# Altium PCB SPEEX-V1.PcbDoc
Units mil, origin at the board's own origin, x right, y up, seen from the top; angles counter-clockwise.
Board outline 3563 x 2400 mil, 2 copper layers (Top Layer, Bottom Layer); 127 components, 78 nets, 444 pads, 198 vias.
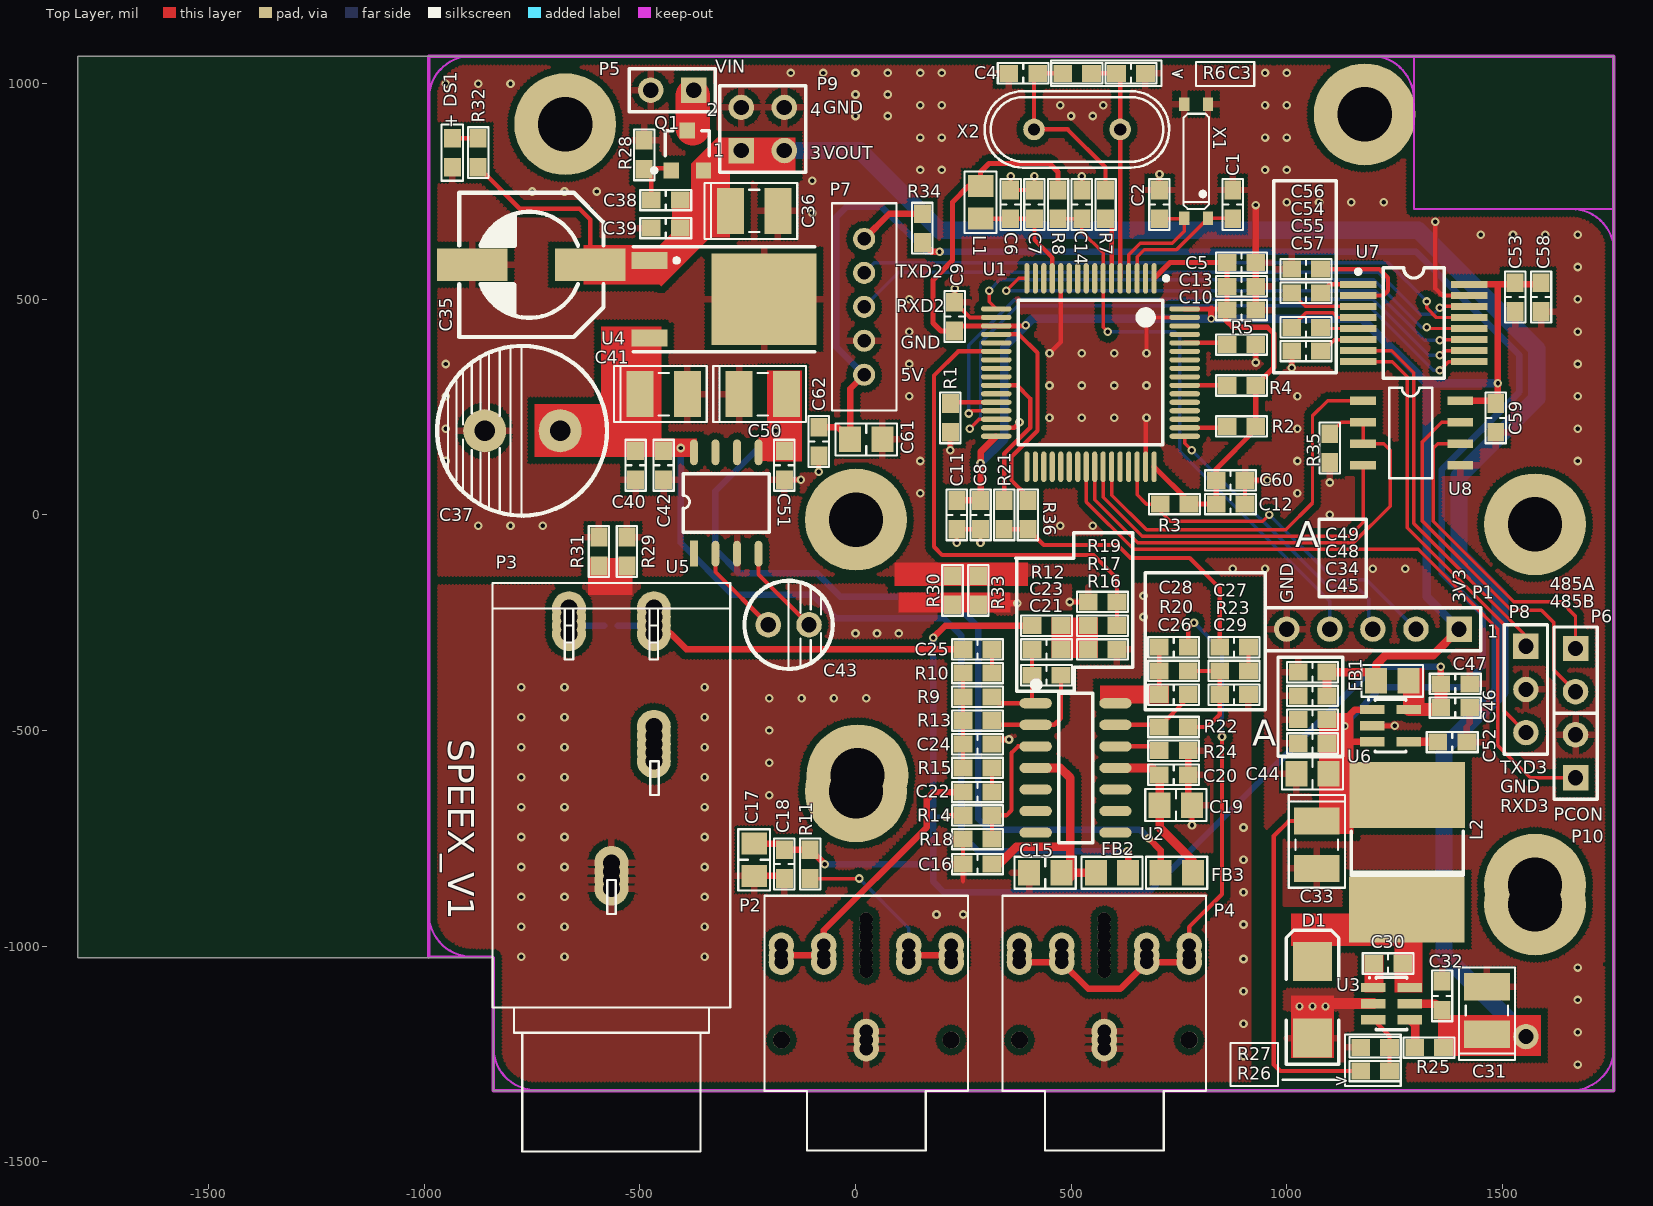
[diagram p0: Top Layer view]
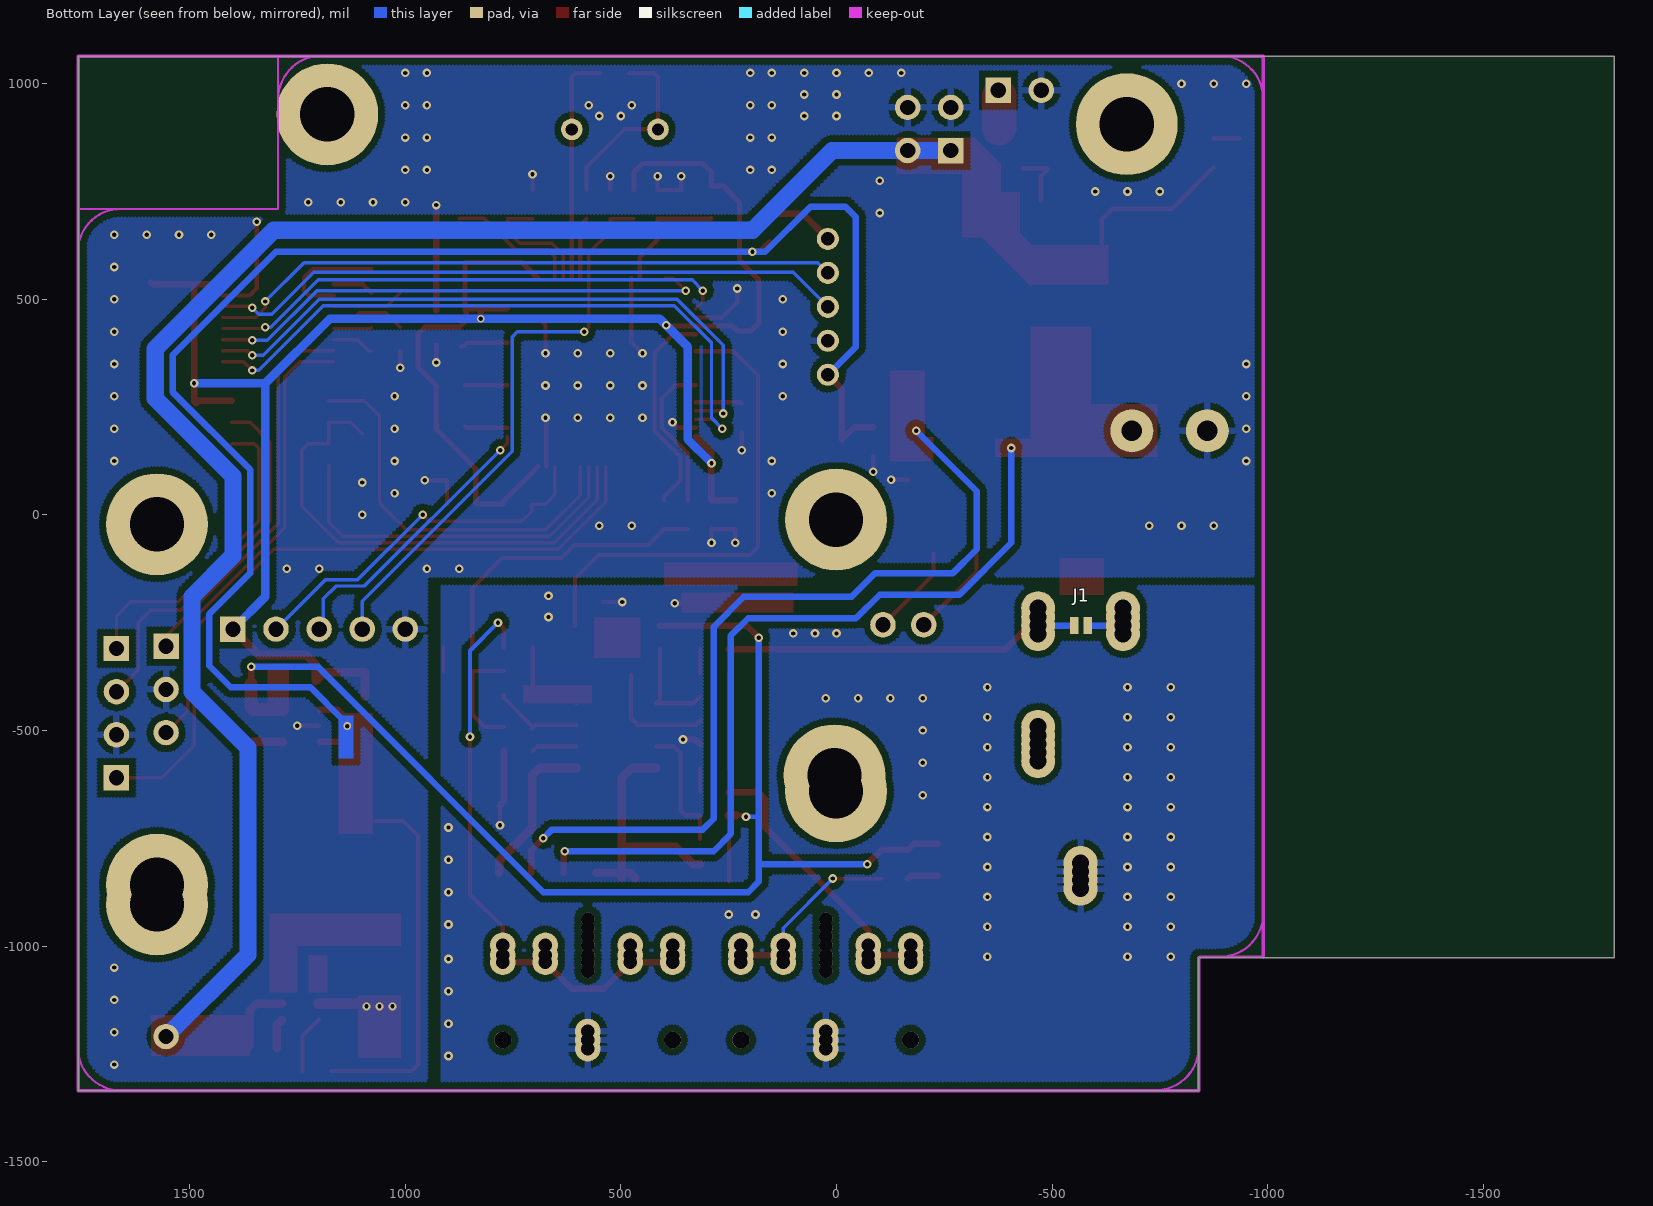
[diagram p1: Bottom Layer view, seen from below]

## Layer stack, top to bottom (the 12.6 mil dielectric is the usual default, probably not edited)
Top Layer: signal copper 1.4
Dielectric: dielectric 12.6, FR-4, Dk 4.8
Bottom Layer: signal copper 1.4

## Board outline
-1804,1064 -1804,-1026 -1803,-1027 -840,-1027 -840,-1336 1759,-1336 1759,1064

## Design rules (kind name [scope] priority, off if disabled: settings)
Clearance Clearance_1 [INPOLYGON] p1: gap=15
Clearance [All] p2: gap=7
ComponentClearance [All] p1: gap=0 collisioncheckmode=3 verticalgap=0 showdistances=FALSE
FabricationTestpoint [(IsPad And (OnTopLayer Or OnBottomLayer))] p1: side=3 testpointundercomponent=TRUE minsize=40 maxsize=100 preferedsize=60 minholesize=0 maxholesize=40 preferedholesize=32 testpointgrid=1 allowsidetop=TRUE allowsidebottom=TRUE usegrid=TRUE gridtolerance=0.01
HoleSize [All] p1: absolutevalues=TRUE maxlimit=200 minlimit=1 maxpercent=80.000 minpercent=20.000
PolygonConnect [IsVia] p1: connectstyle=Direct reliefconductorwidth=10 reliefentries=4 polygonreliefangle="90 Angle"
PolygonConnect PolygonConnect_1 [All] p2: connectstyle=Relief reliefconductorwidth=15 reliefentries=4 polygonreliefangle="90 Angle"
RoomDefinition mcu [InComponentClass('mcu')] p1 off: confinementstyle=ConfineIn formatcopy=TRUE lockcomponents=FALSE outline 4067,1338 4262,1338 4262,1593 4067,1593
RoomDefinition rs232_485 [InComponentClass('rs232_485')] p2 off: confinementstyle=ConfineIn formatcopy=TRUE lockcomponents=FALSE outline 2712,308 5982,308 5982,913 2712,913
RoomDefinition power [InComponentClass('power')] p3 off: confinementstyle=ConfineIn formatcopy=TRUE lockcomponents=FALSE outline 4147,-252 4382,-252 4382,-2 4147,-2
RoomDefinition audio_inout [InComponentClass('audio_inout')] p4 off: confinementstyle=ConfineIn formatcopy=TRUE lockcomponents=FALSE outline 3092,-1387 10067,-1387 10067,-677 3092,-677
RoutingVias [All] p1: holewidth=10 width=20 viastyle="Through Hole" minholewidth=8 minwidth=15 maxholewidth=28 maxwidth=50
SilkscreenOverComponentPads [All] p1: minsilkscreentomaskgap=10
SolderMaskExpansion [All] p1: expansion=4
Width [All] p1: maxlimit=100 minlimit=8 preferedwidth=10
24 further rules are at their usual default settings.

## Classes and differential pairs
component class mcu: C1 C2 C3 C4 C5 C6 C7 C8 C9 C10 C11 C12 C13 C14 C60 C? D? DS? FB? L1 L? P1 P? Q? R1 R2 R3 R4 R5 R6 R7 R8 R? U1 U? X1 X2 X?
component class audio_inout: C15 C16 C17 C18 C19 C20 C21 C22 C23 C24 C25 C26 C27 C28 C29 J1 P2 P3 P4 R9 R10 R11 R12 R13 R14 R15 R16 R17 R18 R19 R20 R21 R22 R23 R24 R36 U2
component class rs232_485: C5 C53 C54 C55 C56 C58 C59 C61 C62 P6 P7 P8 P9 P10 R1 R35 U1 U8
component class power: C6 C7 C31 C33 C34 C35 C36 C37 C38 C39 C40 C41 C42 C43 C44 C45 C46 C47 C48 C49 C50 C51 C52 D1 DS1 FB1 FB2 FB3 L1 P5 Q1 R5 R25 R26 R27 R29 R30 R31 R32 R33 U3 U4 U5 U6

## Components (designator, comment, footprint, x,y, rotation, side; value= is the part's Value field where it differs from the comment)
C1 "6.8pF" C-0603 875,720 r90 top
C2 "6.8pF" C-0603 705,720 r90 top
C3 "20pF" C-0603 639,1024 r0 top
C4 "20pF" C-0603 389,1024 r180 top
C5 "100nF" C-0603 895,585 r180 top
C6 "1uF" C-0603 360,720 r270 top
C7 "100nF" C-0603 415,720 r270 top
C8 "100nF" C-0603 290,0 r90 top
C9 "100nF" C-0603 230,460 r270 top
C10 "100nF" C-0603 895,475 r180 top
C11 "100nF" C-0603 235,0 r90 top
C12 "100nF" C-0603 870,25 r180 top
C13 "10uF" C-0603 895,530 r180 top
C14 "104" C-0603 525,720 r270 top
C15 "10uF" C-0805 440,-830 r180 top
C16 "0.1uF" C-0603 283,-810 r0 top
C17 "10uF" C0805 -235,-800 r90 top
C18 "0.1uF" C-0603 -165,-810 r90 top
C19 "10uF" C-0805 743,-673 r180 top
C20 "0.1uF" C-0603 738,-603 r180 top
C21 "500pF" C-0603 443,-372 r180 top
C22 "10uF" C-0603 283,-643 r0 top
C23 "10uF" C-0603 443,-312 r180 top
C24 "1nF" C-0603 283,-532 r180 top
C25 "10uF" C-0603 283,-312 r0 top
C26 "20pF" C-0603 738,-417 r180 top
C27 "10uF" C-0603 878,-307 r0 top
C28 "10uF" C-0603 738,-307 r0 top
C29 "1nF" C-0603 878,-417 r180 top
C30 "2.2nF" C-0603 1235.46,-1040.54 r0 top
C31 "10uF/25V" C-1210 1464.46,-1149.54 r90 top
C32 "0.01uF" C-0603 1360.46,-1115.54 r270 top
C33 "100uF/6.3V" C-1210 1070,-765 r270 top
C34 "0.01uF" C-0603 1060,-475 r0 top
C35 "220uF/25V" ECAP_SMD_8.5MM -615,580 r270 top
C36 "10uF/25V" C-1210 -235,705 r0 top
C37 "100uF/25V" CAP -775,195 r180 top
C38 "10uF" C-0603 -440,730 r0 top
C39 "0.1uF" C-0603 -440,665 r0 top
C40 "0.1uF" C-0603 -510,115 r90 top
C41 "10uF/16V/B型" C-1210 -445,280 r0 top
C42 "0.1uF" C-0603 -445,115 r90 top
C43 "10uF" CAP0.5 -155,-255 r0 top
C44 "10uF" C0805 1060,-600 r180 top
C45 "1nF" C-0603 1060,-530 r180 top
C46 "100u" C-0603 1391,-447 r0 top
C47 "100uF" C-0603 1391,-392 r0 top
C48 "10u" C-0603 1060,-420 r180 top
C49 "1nF" C-0603 1060,-365 r180 top
C50 "10uF/16V/B型" C-1210 -215,280 r0 top
C51 "0.1uF" C-0603 -165,115 r90 top
C52 "103" C-0603 1384,-527 r0 top
C53 "0.1uF" C-0603 1530,505 r270 top
C54 "0.1uF" C-0603 1045,515 r180 top
C55 "0.1uF" C-0603 1045,435 r0 top
C56 "0.1uF" C-0603 1045,570 r180 top
C57 "0.1uF" C-0603 1045,380 r0 top
C58 "10uF" C-0603 1590,505 r270 top
C59 "0.01uF" C-0603 1485,225 r270 top
C60 "10nF" C0603 870,80 r180 top
C61 "10uF" C-0805 25,175 r180 top
C62 "0.1uF" C-0603 -85,170 r90 top
D1 "IN5819" SMB 1060,-1125 r90 top
DS1 "红色LED" Led-0603 -935,840 r270 top
FB1 "0R" R-0805 1245,-385 r180 top
FB2 "0R" R-0805 595,-830 r180 top
FB3 "0R" R-0805 745,-830 r0 top
J1 "NC" CON_PAD2 -583,-252 r270 bottom
L1 "FB1" R-0805 290,725 r270 top
L2 "10uH(30005061)" C2225 1280,-785 r270 top
P1 "MHDR1X5" HDR1X5 1400,-265 r180 top
P2 "PJ-317音频座" PJ-317 25,-1218 r0 top locked
P3 "会议话筒" PJ-603(A)-2 -566,-847 r0 top locked
P4 "PJ-317音频座" PJ-317 577,-1218 r0 top locked
P5 "Header 2" HDR1X2 -375,985 r180 top
P6 "Header 2" HDR1X2 1670,-310 r270 top
P7 "2.0间距单排母1x5" PIN5 20,325 r90 top
P8 "Header 3" HDR1X3 1555,-305 r270 top
P9 "MHDR2X2" HDR2X2 -265,845 r0 top
P10 "Header 2" HDR1X2 1670,-610 r90 top
Q1 "AO3401" SOT23A -390,845 r0 top
R1 "10K" R0603 220,225 r270 top
R2 "10K" R-0603 895,205 r180 top
R3 "10K" R-0603 740,25 r180 top
R4 "10K" R-0603 895,300 r180 top
R5 "10K" R-0603 895,395 r0 top
R6 "1M" R-0603 514,1024 r0 top
R7 "0R" R-0603 580,720 r90 top
R8 "1K" R-0603 470,720 r90 top
R9 "100K" R-0603 283,-422 r0 top
R10 "30K" R-0603 283,-367 r180 top
R11 "2K" R-0603 -105,-810 r270 top
R12 "100K" R-0603 443,-257 r0 top
R13 "20K" R-0603 283,-477 r180 top
R14 "0R" R-0603 283,-697 r0 top
R15 "10K" R-0603 283,-587 r180 top
R16 "100K" R-0603 573,-312 r0 top
R17 "1K" R-0603 573,-257 r0 top
R18 "1K" R-0603 283,-752 r180 top
R19 "1K" R-0603 573,-202 r180 top
R20 "100K" R-0603 738,-362 r180 top
R21 "0R/NC" R-0603 345,0 r270 top
R22 "20K" R-0603 738,-492 r0 top
R23 "51K" R-0603 878,-362 r180 top
R24 "1K" R-0603 738,-547 r0 top
R25 "100K" R-0603 1330.46,-1235.54 r180 top
R26 "51K/1%" R-0603 1205,-1290 r0 top
R27 "10K/1%" R-0603 1205,-1235 r180 top
R28 "100R" R-0603 -490,835 r90 top
R29 "0R" R-0603 -530,-85 r90 top
R30 "0R" R-0603 225,-175 r90 top
R31 "0R" R-0603 -595,-85 r90 top
R32 "10K" R-0603 -875,840 r90 top
R33 "0R" R-0603 285,-175 r90 top
R34 "10K/NC" R-0603 155,665 r270 top
R35 "4.7K" R-0603 1100,155 r270 top
R36 "0R" R-0603 400,0 r270 top
U1 "STM32F103RBT6" LQFP64_N 545,330 r270 top locked
U2 "OPA4227" D014_L 418,-437 r0 top
U3 "MP2359" SOT23-6 1243.46,-1133.54 r270 top
U4 "L78M09CDT" TO-252 -345,500 r270 top
U5 "LTC1144IS8" SO-8 -375,-90 r0 top
U6 "MIC5205-3.3" SOT23-5 1241,-489 r270 top
U7 "MAX3232EEAE" SSOP16 1295,445 r270 top
U8 "MAX3485EESA(SO8)" SO8 1290,190 r270 top
X1 "MC306-G-06Q-32.768 (manufacturer JFVNY)" 32.768K-MC146 790,820 r90 top
X2 "8MHz" XTAL-CJ 614,894 r0 top

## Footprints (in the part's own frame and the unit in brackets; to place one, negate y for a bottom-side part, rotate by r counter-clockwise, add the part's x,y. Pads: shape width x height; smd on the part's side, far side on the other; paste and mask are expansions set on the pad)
32.768K-MC146 [mm] "XTAL-32.768K"
  rect 0.8x0.6 smd: 1(-3.35,-0.7) 2(3.35,-0.7) 3(3.35,0.7) 4(-3.35,0.7)
  silkscreen extent -2.8,-0.75 2.8,0.75
C0603 [mm]
  rect 1.1x1 smd: 1(-0.85,0) 2(0.85,0)
  silkscreen extent -1.5,-0.6 1.5,0.6
C0805 [mm]
  rect 1.3x1.5 smd: 1(-0.95,0) 2(0.95,0)
  silkscreen extent -1.8,-0.94 1.8,0.94, body extent -1.02,-0.58 0.98,0.62, height 1.2
C2225 [mm] "Chip Capacitor; Body 5.6 x 6.4 mm (LxW typ)"
  rect 3.9x6.8 smd: 1(3.302,-0.025) 2(-3.429,0)
  silkscreen extent -1.3,-3.3 1.3,3.3, body extent -2.86,-2.6 2.86,2.6, height 4.5
C-0603 [mm]
  rect 1.1x1 smd: 1(-0.85,0) 2(0.85,0)
  silkscreen extent -1.5,-0.6 1.5,0.6, body extent -0.81,-0.41 0.79,0.39, height 0.6
C-0805 [mm]
  rect 1.3x1.5 smd: 1(-0.95,0) 2(0.95,0)
  silkscreen extent -1.8,-0.94 1.8,0.94
C-1210 [mm]
  rect 1.6x2.7 smd: 1(-1.4,0) 2(1.4,0)
  silkscreen extent -2.92,-1.65 2.54,1.65, body extent -1.75,-1.4 1.75,1.4, height 1.9
CAP [mil] "180uF,330uF"
  round 100 hole 47.24: 1(-90,0) 2(85,0)
  silkscreen extent -199,-197 195,200
CAP0.5 [mm] "47uF"
  round 1.5 hole 0.9: 1(-1.2,0) 2(1.2,0)
  silkscreen extent -2.6,-2.6 2.6,2.6, body extent -3.18,-3.1 3.17,3.25, height 13.03
CON_PAD2 [mm]
  rect 1x0.5 smd: 1(0.127,0) 2(0.127,-0.8)
D014_L [mm]
  oval 1.9x0.6 smd: 1(0,0) 2(0,-1.27) 3(0,-2.54) 4(0,-3.81) 5(0,-5.08) 6(0,-6.35) 7(0,-7.62) 8(4.7,-7.62) 9(4.7,-6.35) 10(4.7,-5.08) 11(4.7,-3.81) 12(4.7,-2.54) 13(4.7,-1.27) 14(4.7,0)
  silkscreen extent -0.1,-8.21 3.35,1.22, body extent -0.66,-8.16 5.33,0.54, height 1.55
ECAP_SMD_8.5MM [mm] "铝电解电容"
  rect 1.9x4.15 smd: 1(0,0) 2(0,-6.95)
  silkscreen extent -4.25,-7.72 4.25,0.77, body extent -3.3,-7.31 3.3,-0.31, height 7.7
HDR1X2 [mm] "Connector; Header; 2 Position"
  rect 1.5x1.5 hole 0.9: 1(0,0)
  round 1.5 hole 0.9: 2(2.54,0)
  silkscreen extent -1.27,-1.27 3.81,1.27, body extent -1.27,-1.27 3.81,1.27, height 7.58
HDR1X3 [mm] "Connector; Header; 3 Position"
  rect 1.5x1.5 hole 0.9: 1(0,0)
  round 1.5 hole 0.9: 2(2.54,0) 3(5.08,0)
  silkscreen extent -1.27,-1.27 6.35,1.27, body extent -1.27,-1.27 6.35,1.27, height 7.58
HDR1X5 [mm] "Connector; Header; 5 Position"
  rect 1.5x1.5 hole 0.9: 1(0,0)
  round 1.5 hole 0.9: 2(2.54,0) 3(5.08,0) 4(7.62,0) 5(10.16,0)
  silkscreen extent -1.27,-1.27 11.43,1.27, body extent -1.27,-1.27 11.43,1.27, height 7.58
HDR2X2 [mm] "Connector; Header; 2x2 Position"
  rect 1.5x1.5 hole 0.9: 1(0,0)
  round 1.5 hole 0.9: 2(0,2.54) 3(2.54,0) 4(2.54,2.54)
  silkscreen extent -1.27,-1.27 3.81,3.81, body extent -1.27,-1.27 3.81,3.81, height 7.58
Led-0603 [mm]
  rect 1.1x1 smd: 1(-0.85,0) 2(0.85,0)
  silkscreen extent -1.65,-0.64 1.65,0.64, body extent -1.02,-0.45 1.04,0.45, height 0.85
LQFP64_N [mm] "Thin QFP, 64-Leads, Body 10x10mm, Pitch 0.5mm, IPC Medium Density"
  oval 1.8x0.3 smd: 1(-5.55,3.75) 2(-5.55,3.25) 3(-5.55,2.75) 4(-5.55,2.25) 5(-5.55,1.75) 6(-5.55,1.25) 7(-5.55,0.75) 8(-5.55,0.25) 9(-5.55,-0.25) 10(-5.55,-0.75) 11(-5.55,-1.25) 12(-5.55,-1.75) 13(-5.55,-2.25) 14(-5.55,-2.75) 15(-5.55,-3.25) 16(-5.55,-3.75) 33(5.55,-3.75) 34(5.55,-3.25) 35(5.55,-2.75) 36(5.55,-2.25) 37(5.55,-1.75) 38(5.55,-1.25) 39(5.55,-0.75) 40(5.55,-0.25) 41(5.55,0.25) 42(5.55,0.75) 43(5.55,1.25) 44(5.55,1.75) 45(5.55,2.25) 46(5.55,2.75) 47(5.55,3.25) 48(5.55,3.75)
  oval 0.3x1.8 smd: 17(-3.75,-5.55) 18(-3.25,-5.55) 19(-2.75,-5.55) 20(-2.25,-5.55) 21(-1.75,-5.55) 22(-1.25,-5.55) 23(-0.75,-5.55) 24(-0.25,-5.55) 25(0.25,-5.55) 26(0.75,-5.55) 27(1.25,-5.55) 28(1.75,-5.55) 29(2.25,-5.55) 30(2.75,-5.55) 31(3.25,-5.55) 32(3.75,-5.55) 49(3.75,5.55) 50(3.25,5.55) 51(2.75,5.55) 52(2.25,5.55) 53(1.75,5.55) 54(1.25,5.55) 55(0.75,5.55) 56(0.25,5.55) 57(-0.25,5.55) 58(-0.75,5.55) 59(-1.25,5.55) 60(-1.75,5.55) 61(-2.25,5.55) 62(-2.75,5.55) 63(-3.25,5.55) 64(-3.75,5.55)
  silkscreen extent -5.67,-4.25 4.25,4.58, body extent -5,-5 5,5, height 1.6
PIN5 [mm] "Connector; Plug"
  round 1.3 hole 0.8: 1(0,0) 2(2,0) 3(4,0) 4(6,0) 5(8,0)
  silkscreen extent -2.1,-1.91 10.1,1.9
PJ-317 [mm] "音频座"
  round 1.5 hole 0.8: 1(0,-0.508) 1(0,0) 1(0,0.508) 2(-5,4.572) 2(-5,5) 2(-5,5.588) 3(-2.5,4.572) 3(-2.5,5) 3(-2.5,5.588) 4(2.5,4.572) 4(2.5,5) 4(2.5,5.588) 5(5,4.572) 5(5,5) 5(5,5.588)
  round 1 hole 1: 6(-5,0) 7(5,0)
  round 0.8 hole 0.8: 8(0,4.064) 8(0,4.572) 8(0,5) 8(0,5) 8(0,5.588) 8(0,6.096) 8(0,6.604) 8(0,7.112)
  silkscreen extent -6,-6.5 6,8.5, body extent -6.05,-6.55 6.05,8.55, height 3.2
PJ-603(A)-2 [mm] "会议话筒音频座"
  round 2 hole 1: 1(0,-0.508) 1(0,0) 1(0,0.508) 1(0,1.016) 2(-2.5,14.492) 2(-2.5,15) 2(-2.5,15.508) 2(-2.5,16.016) 3(2.5,14.492) 3(2.5,15) 3(2.5,15.508) 3(2.5,16.016) 4(2.5,7) 4(2.5,7.508) 4(2.5,8.016) 4(2.5,8.524) 4(2.5,9.032)
  silkscreen extent -7,-16 7,17.5
R0603 [mm]
  rect 1.1x1 smd: 1(-0.85,0) 2(0.85,0)
  silkscreen extent -1.5,-0.6 1.5,0.6
R-0603 [mm]
  rect 1.1x1 smd: 1(-0.85,0) 2(0.85,0)
  silkscreen extent -1.5,-0.6 1.5,0.6, body extent -0.8,-0.42 0.8,0.38, height 0.45
R-0805 [mm]
  rect 1.3x1.5 smd: 1(-0.95,0) 2(0.95,0)
  silkscreen extent -1.8,-0.94 1.8,0.94, body extent -0.99,-0.61 1.01,0.65, height 0.55
SMB [mm] "DO-214-AA/SMB; 2 C-Bend Leads; Body 5.3 x 3.6 mm, inc. leads (LxW)"
  rect 2.3x2.3 smd: 1(-2.25,0) 2(2.25,0)
  silkscreen extent -3.8,-1.55 4.1,1.55, body extent -2.72,-1.98 2.88,1.92, height 2.5
SO8 [mil]
  rect 20x60 smd: 1(-75,-112.5) 2(-25,-112.5) 3(25,-112.5) 4(75,-112.5) 5(75,112.5) 6(25,112.5) 7(-25,112.5) 8(-75,112.5)
  silkscreen extent -105,-53 105,48, body extent -96,-117 97,119, height 67
SO-8 [mil]
  rect 18x60 smd: 1(0.25,0)
  oval 18x60 smd: 2(50.25,0) 3(100.25,0) 4(150.25,0) 5(150.25,235) 6(100.25,235) 7(50.25,235) 8(0.25,235)
  silkscreen extent -25,50 175,185, body extent -21,-5 172,231, height 67
SOT23-5 [mm]
  rect 0.55x1.45 smd: 1(-0.95,-1.075) 2(0,-1.075) 3(0.95,-1.075) 4(0.95,1.075) 5(-0.95,1.075)
  silkscreen extent -1.57,-1.35 1.55,0.9, body extent -1.45,-1.4 1.45,1.4, height 1.2
SOT23-6 [mm] "SOT-23/SC-74A; 5 Leads; Body 3.1 x 3 mm, inc. leads (LxW max)"
  rect 0.55x1.45 smd: 1(-0.95,-1.075) 2(0,-1.075) 3(0.95,-1.075) 4(0.95,1.075) 5(0,1.075) 6(-0.95,1.075)
  silkscreen extent -1.57,-1.35 1.55,0.9, body extent -1.4,-1.24 1.4,1.18, height 1.08
SOT23A [mm] "SOT-23; 3 Leads; Body 3.0 x 2.5 mm, inc. leads (LxW max)"
  rect 0.9x0.95 smd: 1(-0.95,-1.175) 2(0.95,-1.175) 3(0,1.175)
  silkscreen extent -2.07,-1.3 1.3,1.18, body extent -1.45,-1.42 1.45,1.38, height 1.2
SSOP16 [mm] "SSOP; 16 Leads; Body Width 5.3 mm; Pitch 0.65 mm"
  rect 0.4x2.15 smd: 1(-2.275,-3.275) 2(-1.625,-3.275) 3(-0.975,-3.275) 4(-0.325,-3.275) 5(0.325,-3.275) 6(0.975,-3.275) 7(1.625,-3.275) 8(2.275,-3.275) 9(2.275,3.275) 10(1.625,3.275) 11(0.975,3.275) 12(0.325,3.275) 13(-0.325,3.275) 14(-0.975,3.275) 15(-1.625,3.275) 16(-2.275,3.275)
  silkscreen extent -3.25,-3.4 3.25,1.8, body extent -2.49,-3.28 2.51,3.18, height 1.2
TO-252 [mm] "D-PAK/TO-252-AA; 3 Leads (1 Cropped); Body 10.1 (inc. leads) x 6.6 mm (LxW max)"
  rect 1x2.1 smd: 1(-2.285,-3.375) 3(2.285,-3.375)
  rect 5.4x6.2 smd: 4(0,3.375)
  silkscreen extent -3.09,-4.32 3.09,6.38, body extent -3.27,-3.96 3.27,5.98, height 2.39
XTAL-CJ [mil]
  round 50 hole 28: 1(0,0) 2(-200,0)
  silkscreen extent -315,-89 114,89, body extent -326,-92 126,91, height 138

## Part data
C1 C2 C3 C4 C5: library part CAP, "Capacitor"
C6 C7 C8 C9 C10 C11 C12 C13 C14 C30 C32 C34 C38 C45 C46 C47 C48 C49 C52 C58 C59 C60: library part Cap, "Capacitor"
C15 C17 C19 C31 C35 C36 C37 C41 C43 C50 C53 C54 C55 C56 C57 C61: library part "Cap Pol1", "Polarized Capacitor (Radial)"
C16 C18 C20 C23 C25 C27 C28 C39 C40 C42 C51 C62: library part CAP
C21 C24 C26 C29: library part "Cap Pol2", "Polarized Capacitor (Axial)"
C22: library part Cap
C33: library part Cap2, "Capacitor"
C44: library part "Cap Pol3", "Polarized Capacitor (Surface Mount)"
D1: library part "D Schottky", "Schottky Diode"
DS1: library part Lamp, "Incandescent Bulb"
FB1 FB2 FB3: library part FB
J1: library part "Header 2", "Header, 2-Pin"
L1 L2: library part Inductor, "Inductor"
P1: "Header, 5-Pin"
P2 P4: library part PJ-317
P3: library part MIC
P5 P6 P10: "Header, 2-Pin"
P7: library part "Header 5", "Header, 5-Pin"
P8: "Header, 3-Pin"
P9: "Header, 2-Pin, Dual row"
R1 R5 R6: library part res1, "Resistor"
R2 R3 R4 R9 R10 R12 R13 R14 R15 R16 R17 R18 R19 R20 R21 R22 R23 R24 R36: library part RES
R7 R8: library part Res3, "Resistor"
R11 R29 R30 R31 R33: library part RES2
R25 R26 R27 R28 R34: library part Res2, "Resistor"
R32: library part "Res Semi", "Semiconductor Resistor"
R35: library part RESISTOR_Dup1, "RES,5%,1/10W,SMD0603"
U1: "STM32 ARM-based 32-bit MCU with 128 Kbytes Flash, 64-pin LQFP, Industrial Temperature"
U4: "Positive Voltage Regulator"
U6: library part MIC5205, "800mA Low Dropout Positive Regulator Fixed 2.85V,3V,3.3V and 5V"
U7: "?5kV ESD-Protected, 3.0V to 5.5V, Low-Power, up to 250kbps, True RS-232 Transceiver"
U8: library part MAX485E
X1: library part MC306
X2: library part CRYSTAL, "Crystal"

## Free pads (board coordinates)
  round 236.22 hole 125.98: 0(1576.04,-903.75) 0(1576.04,-21.83) 1(1576.05,-857.82) 2(1.04,-11.16) 3(4.71,-604.08) 4(1.04,-641.08) 9(-673.29,906.09) 10(1181.04,928.84)
  round 59.06 hole 35.43: 1(1555,-1210)

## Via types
v1: diameter 20, hole 10, Top Layer to Bottom Layer, 193 vias
v2: diameter 18, hole 10, Top Layer to Bottom Layer, 5 vias

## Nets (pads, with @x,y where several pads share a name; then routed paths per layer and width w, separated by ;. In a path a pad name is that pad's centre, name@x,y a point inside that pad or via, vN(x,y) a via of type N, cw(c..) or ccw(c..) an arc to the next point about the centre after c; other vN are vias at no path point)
9V: C15.1 C16.2 FB2.2 U2.4 | length 615.1
  Top Layer w20: C16.2 333.4,-810 373.4,-770 498,-770 ; U2.4 475,-587 498,-610 C15.1@498,-841 ; C15.1@466.46,-843 479.46,-830 FB2.2
485_CON: R35.1 U1.41 U8.2 U8.3 | length 1175.4
  Top Layer w8: U1.41 554.84,35.16 655,-65 1155,-65 1240,20 1240,150 1225,165 U8.3 U8.2 1126.54,215 R35.1
485_RXD: U1.43 U8.1 | length 925.3
  Top Layer w8: U1.43 594.21,45.79 675,-35 997.5,-35 1060,27.5 1060,230 1095,265 U8.1
485_TXD: U1.42 U8.4 | length 857.4
  Top Layer w8: U1.42 574.53,40.47 665,-50 1145,-50 1177.5,-17.5 U8.4
485A: P6.1 U8.6 | length 732.8
  Top Layer w8: U8.6 1350,165 1340,155 1340,-15 1527,-202 1637,-202 1670,-235 P6.1
485B: P6.2 U8.7 | length 874.2
  Top Layer w8: U8.7 1360,215 1315,170 1315,-15 1521,-221 1591,-221 1620,-250 1620,-360 P6.2
-9V: C19.2 C20.2 FB3.2 U2.11 | length 367.4
  Top Layer w15: C20.2 C20.2@705.6,-604.06
  Top Layer w20: U2.11 688.54,-587 C20.2 ; C20.2@705.6,-604.06 705.6,-725.6 782.4,-802.4 FB3.2
/RST: C14.2 P1.4 R8.1 U1.7 | length 1335.5
  Top Layer w8: R8.1 C14.2 525,657 574.53,607.47 574.53,435.47 v1(585,425)
  Bottom Layer w8: v1(585,425) 740,425 752.5,412.5 752.5,147.5 1100,-200 P1.4
A3V3: C17.2 C18.2 C46.1 C47.1 FB1.1 R11.1 R12.1 R14.1 U6.5 | length 2902.1
  Top Layer w10: v1(210,-700) 213,-697 R14.1
  Top Layer w15: C17.2 -178.94,-762.6 C18.2 R11.1 v1(-71.54,-810) ; v1(180,-285) 208,-257 R12.1 ; C47.1 v1(1357.54,-352.46)
  Top Layer w20: R14.1@234,-697 R14.1
  Top Layer w30: U6.5 1352.94,-451.6 C46.1 C47.1
  Bottom Layer w10: 180,-700 v1(210,-700)
  Bottom Layer w15: v1(-71.54,-810) 180,-810 ; v1(180,-285) 180,-850 205,-875 680,-875 1202.54,-352.46 v1(1357.54,-352.46)
ADC: R17.2 R19.1 U1.22 | length 1129.2
  Top Layer w10: U1.22 238.21,379.21 182,323 182,-74 201,-93 552,-93 606.46,-147.46 R19.1 R17.2
AGND: C15.2 C16.1 C17.1 C18.1 C19.1 C20.1 C24.1 C29.1 P2.1 P3.1 P4.1 R16.2 R18.2 R19.2 R24.2 R29.1 R30.1 R31.1 R33.1 | length 458.4
  Top Layer w10: 249.54,-849.54 C16.1 R18.2 ; v1(497,-202) R19.2 ; v1(780.4,-720) C19.1
  Top Layer w15: C17.1 -171.06,-837.4 C18.1 ; C24.1 327.46,-521 v1(356,-521) ; 350,-205 v1(375,-205) ; R24.2 C20.1 771.46,-664.06 C19.1
  other v1: 900,-1255 900,-1180 900,-1105 900,-1030 -775,-1025 -675,-1025 -350,-1025 -775,-955.56 -675,-955.56 -350,-955.56 900,-950 188,-927 250,-927 -775,-886.11 -675,-886.11 -350,-886.11 900,-875 -775,-816.67 -675,-816.67 -350,-816.67 900,-800 -775,-747.22 -675,-747.22 -350,-747.22 900,-725 -775,-677.78 -675,-677.78 -350,-677.78 -200,-650 -775,-608.33 -675,-608.33 -350,-608.33 -200,-575 -775,-538.89 -675,-538.89 -350,-538.89 -200,-500 -775,-469.44 -675,-469.44 -350,-469.44 -200,-425 -125,-425 -50,-425 25,-425 -775,-400 -675,-400 -350,-400 0,-275 50,-275 100,-275 668,-237 668,-188
AUDIO: C23.1 R12.2 R16.1 R17.1 | length 236.1
  Top Layer w10: C23.1 R12.2 R17.1 R16.1 C23.1
AUDIO2: C25.2 R10.1 | length 55
  Top Layer w10: R10.1 C25.2
BOOT0: R5.1 U1.60 | length 110.2
  Top Layer w10: U1.60 857.64,398.9 866.54,390 R5.1@870,390
BOOT1: R1.1 U1.28 | length 107.6
  Top Layer w10: R1.1 222.64,261.1 U1.28
D3V3: C5.2 C8.2 C9.2 C10.2 C11.2 C12.2 C13.2 C48.1 C49.1 C53.1 C58.1 C59.1 C60.2 FB1.2 L1.1 P1.1 R2.1 R3.1 R4.1 R8.2 U1.1 U1.19 U1.32 U1.48 U1.64 U7.16 U8.8 | length 5399.1
  Top Layer w12: v1(395,440) 393.27,438.27 241.73,438.27 C9.2 198.46,426.54 180,445 180,545 225,590 225,725 262.4,762.4 L1.1 290,795 310,815 450,815 470,795 R8.2 ; U1.48 773.46,30.67 R3.1 C12.2 836.54,106.54 928.46,198.46 R4.1 970,341.54 970,420 955,435 875,435 858.9,451.1 C10.2@858.9,477.64 ; U1.1 729.13,585 C5.2 C10.2 C10.2@858.9,477.64 ; U1.64 C10.2@858.9,477.64
  Top Layer w15: C11.2 C8.2 290,145.87 U1.32@325.78,181.64 ; v2(825,455) 825,477.64 ; U8.8 1488.46,265 C59.1@1490,263.46 ; U7.16 1586.1,534.57 C58.1 ; C59.1 C59.1@1490,263.46 ; 1490,534.57 C59.1@1490,263.46
  Top Layer w20: C48.1 C49.1 1187.6,-365 FB1.2 1207.6,-347.4 1230,-325 1340,-325 P1.1
  Bottom Layer w20: v1(290,120) 345,175 345,390 410,455 1175,455 1325,305 ; P1.1 1325,-190 1325,305 ; v1(1490,305) 1325,305
D5V: C33.1 C34.2 C44.1 C45.1 C61.2 C62.2 L2.2 P7.1 R26.1 R34.2 U6.1 U6.3 | length 4606.9
  Top Layer w10: C33.1 1005.12,-709.88 970,-745 970,-1275 985,-1290 R26.1
  Top Layer w15: C62.2 -40.87,203.46 C61.2 -12.4,292.6 P7.1 ; R34.2 176.54,610 v1(195,610) ; 1135,-475 1158.4,-451.6 U6.1 ; 1145,-526.4 U6.3
  Bottom Layer w15: P7.1 -45,390 -45,690 -20,715 60,715 165,610 1300,610 1540,370 1540,285 1360,105 1360,-135 1455,-230 1455,-350 1405,-400 1220,-400 1145,-475 1140,-475
  other v2: 1135,-490
DAC: R36.1 U1.20 | length 496.3
  Top Layer w10: U1.20 379.42,418.58 422,376 422,194.96 362,134.96 362,80 400,42 R36.1
GND: C1.2 C2.2 C3.2 C4.2 C5.1 C6.1 C7.1 C8.1 C9.1 C10.1 C11.1 C12.1 C13.1 C14.1 C31.2 C32.1 C33.2 C34.1 C35.2 C36.2 C37.2 C39.1 C40.1 C41.2 C42.1 C44.2 C45.2 C46.2 C47.2 C48.2 C49.2 C50.1 C51.1 C52.2 C53.2 C56.2 C57.1 C58.2 C59.2 C60.1 C61.1 C62.1 D1.1 DS1.2 P1.5 P5.2 P7.2 P8.2 P9.2 P9.4 P10.2 R1.2 R5.2 R27.2 R28.2 R29.2 R30.2 R31.2 R33.2 R35.2 U1.12 U1.18 U1.31 U1.47 U1.63 U3.2 U4.4 U5.3 U6.2 U7.15 U8.5 X1.2 X1.3 | length 1904.4
  Top Layer w10: C51.1 v1(-126.54,81.54) ; v1(-85,100) C62.1 ; v1(220,150) R1.2 ; v1(230,525) C9.1 265.51,457.95 U1.18 ; v1(235,-65) C11.1 C8.1 v1(290,-65) ; U1.31 368.05,202.05 v1(380.5,214.5) ; v1(360,785) C6.1 C7.1 v1(415,785) ; v1(450,375) 476.1,401.1 U1.12 ; C14.1 v1(525,785) ; U1.47 672.95,222.95 v1(675,225) ; v1(675,375) 675,440 692.95,457.95 U1.63 ; C2.2 v1(705,790) ; C12.1 C60.1 v1(955,80) ; v1(928.46,353.46) R5.2 ; v1(1011.54,341.54) C57.1 ; U6.2@1200.68,-489 v1(1251,-489) ; v1(1345,680) 1345,525 1361.02,508.98 U7.15
  Top Layer w15: C10.1 C13.1 C5.1 v1(928.46,718.46)
  Top Layer w25: 1099.88,-1133.54 U3.2
  other v1: 1675,-1275 1675,-1200 1675,-1125 1675,-1050 875,-125 950,-125 1200,-125 1275,-125 -875,-25 -800,-25 -725,-25 475,-25 550,-25 1100,0 150,50 1025,50 1100,75 -950,125 150,125 1025,125 1675,125 -950,200 1025,200 1675,200 450,225 525,225 600,225 -950,275 125,275 1025,275 1675,275 450,300 525,300 600,300 675,300 -950,350 125,350 1675,350 525,375 600,375 125,425 1675,425 125,500 1675,500 1675,575 1450,650 1525,650 1600,650 1675,650 -100,700 1000,725 1075,725 1150,725 1225,725 -750,750 -675,750 -600,750 -100,775 150,800 200,800 950,800 1000,800 150,875 200,875 950,875 1000,875 0,925 75,925 500,925 550,925 150,950 200,950 475,950 575,950 950,950 1000,950 0,975 75,975 -950,1000 -875,1000 -800,1000 -150,1025 -75,1025 0,1025 75,1025 150,1025 200,1025 950,1025 1000,1025
  other v2: 1030,-1140 1060,-1140 1090,-1140
INA+: R14.2 R18.1 U2.3 | length 300.7
  Top Layer w10: R18.1 R14.2 350,-697 362,-685 362,-552 377,-537 U2.3
INA-: C21.1 R13.1 U2.2 | length 272.5
  Top Layer w10: R13.1@314.46,-476 315.96,-477.5 325.46,-487 U2.2 461,-487 476.46,-471.54 C21.1
IND+: R24.1 U2.12 | length 105.6
  Top Layer w10: U2.12 694.54,-537 R24.1
IND-: C26.1 R22.1 U2.13 | length 210.9
  Top Layer w10: U2.13 698.54,-487 R22.1@707.54,-496 ; R22.1 771.46,-425.07 C26.1
MIC: C22.1 P2.2 P2.3 | length 656.9
  Top Layer w8: P2.3@-90.28,-1021.15 P2.3@-73.43,-1038
  Top Layer w15: P2.2@-171.85,-998 -171.85,-1021.15 P2.3@-90.28,-1021.15 ; P2.3@-73.43,-998 -73.43,-963.43 165,-725 165,-660 182,-643 C22.1
NetC4_1: C4.1 R6.1 R7.2 X2.2 | length 446.6
  Top Layer w10: R6.1 C4.1 414,1015.54 X2.2 492,894 580,806 R7.2
NetC6_2: C6.2 C7.2 L1.2 U1.13 | length 280.6
  Top Layer w10: L1.2 291.06,686.54 C7.2 415,638 456.42,596.58 U1.13
NetC24_2: C24.2 R9.1 R10.2 R13.2 R15.2 | length 220
  Top Layer w10: R15.2 C24.2 R13.2 R9.1 R10.2
NetC27_1: C27.1 R21.2 R36.2 | length 693.4
  Top Layer w10: R21.2 R36.2 436.54,-70 607.54,-70 637.76,-100.22 775.22,-100.22 844.54,-169.54 C27.1
NetC27_2: C27.2 R23.1 | length 55
  Top Layer w10: R23.1 C27.2
NetC29_2: C29.2 R20.1 R22.2 R23.2 | length 259.4
  Top Layer w10: R22.2 816,-492 844.54,-463.46 C29.2 R23.2 R20.1
NetC30_1: C30.1 U3.1 | length 54.7
  Top Layer w20: U3.1 C30.1@1201.14,-1041.39
NetC30_2: C30.2 D1.2 L2.1 U3.6 | length 23.8
  Top Layer w20: C30.2 C30.2@1285.79,-1057.39
NetC38_1: C38.1 Q1.1 R28.1 | length 136.9
  Top Layer w10: C38.1 -473.46,785 R28.1 -487.8,803.74 Q1.1@-432.4,803.74
NetC43_1: C43.1 U5.2 | length 215.7
  Top Layer w10: U5.2 -324.75,-132.5 C43.1
NetC43_2: C43.2 U5.4 | length 213.5
  Top Layer w10: U5.4 -224.75,-138.01 C43.2
NetC52_1: C52.1 U6.4 | length 76.4
  Top Layer w20: U6.4 1353.87,-526.4 C52.1@1358,-530.54
NetC54_1: C54.1 U7.1 | length 95.7
  Top Layer w10: C54.1 1098.03,534.57 U7.1
NetC54_2: C54.2 U7.3 | length 167.6
  Top Layer w8: C54.2 1043.15,483.39 U7.3
NetC55_1: C55.1 U7.4 | length 172.7
  Top Layer w8: C55.1 1044.92,468.39 1106.61,468.39 1117.21,457.79 U7.4
NetC55_2: C55.2 U7.5 | length 88.8
  Top Layer w8: C55.2 1081.26,432.2 U7.5
NetC56_1: C56.1 U7.2 | length 268.3
  Top Layer w10: C56.1 1215,570 1235,550 1235,520 1223.98,508.98 U7.2
NetC57_2: C57.2 U7.6 | length 98.6
  Top Layer w8: C57.2 1084.5,380 1111.12,406.61 U7.6
NetDS1_1: DS1.1 R32.2 | length 60
  Top Layer w10: DS1.1 R32.2
NetP2_4: P2.4 P2.5 R11.2 | length 493.1
  Top Layer w8: R11.2 v1(8.46,-843.46) ; P2.4@123.43,-1021.15 P2.4@123.43,-998 ; P2.5@198.7,-998 P2.5@221.85,-1021.15
  Top Layer w15: P2.4@123.43,-1021.15 P2.5@221.85,-1021.15
  Bottom Layer w8: v1(8.46,-843.46) 123.43,-958.43 P2.4@123.43,-1021.15
NetP5_1: P5.1 Q1.3 | length 75
  Top Layer w80: Q1.3@-377,897 P5.1@-377,972
NetP7_5: P7.5 R34.1 | length 159.2
  Top Layer w15: P7.5 78.5,698.46 R34.1
NetR25_2: R25.2 U3.4 | length 70.7
  Top Layer w20: U3.4 1298,-1183.15 R25.2@1298,-1236.54
NetR26_2: R26.2 R27.1 U3.3 | length 134.5
  Top Layer w10: U3.3 1238.46,-1208.26 R26.2
OSC32_IN: C1.1 U1.3 X1.1 | length 309.4
  Top Layer w8: U1.3 653.27,598.27 670,615 744.45,615 X1.1 873.43,688.11 C1.1
OSC32_OUT: C2.1 U1.4 X1.4 | length 295
  Top Layer w8: U1.4 633.58,603.58 660,630 735,630 762.44,657.44 X1.4 760.87,686.54 C2.1
OSC_IN: C3.1 R6.2 U1.5 X2.1 | length 538.5
  Top Layer w10: R6.2 C3.1 614,1015.54 X2.1 X2.1@612.9,892.9 ; U1.5 X2.1@613.9,893.9
OSC_OUT: R7.1 U1.6 | length 143.9
  Top Layer w10: R7.1 594.21,672.32 U1.6
OUTA: C21.2 C23.2 R9.2 U2.1 | length 236.3
  Top Layer w10: R9.2 331.46,-437 U2.1 409.54,-428.54 C21.2 C23.2
OUTD: C26.2 C28.1 R20.2 U2.14 | length 219.8
  Top Layer w10: U2.14 623.04,-417 C26.2 R20.2 C28.1
PB1: U1.27
PCON: P10.1 U1.40 | length 1639.7
  Top Layer w8: U1.40 535.16,29.84 645,-80 1305,-80 1490,-265 1490,-535 1565,-610 P10.1
PWR9V: C37.1 C40.2 C41.1 C42.2 FB2.1 U4.3 U5.8 | length 1871.6
  Top Layer w15: v1(630,-780) 632.4,-782.4 FB2.1
  Bottom Layer w15: v1(-405,155) -405,-65 -285,-185 -100,-185 -45,-240 205,-240 245,-280 245,-740 285,-780 v1(630,-780)
PWR-9V: C50.2 C51.2 FB3.1 U5.5 | length 1967.6
  Top Layer w15: v1(680,-750) 707.6,-777.6 FB3.1
  Bottom Layer w15: v1(-185,195) -325,55 -325,-80 -270,-135 -90,-135 -35,-190 215,-190 285,-260 285,-705 310,-730 660,-730 v1(680,-750)
RS_RXD2: P7.4 U7.13 | length 1475.3
  Top Layer w8: v1(1325,495) 1325,480 1347.21,457.79 U7.13
  Bottom Layer w8: P7.4 43.78,585 1235,585 v1(1325,495)
RS_RXD3: P8.3 U7.8 | length 1067.5
  Top Layer w8: U7.8 1244.57,355.43 1280,320 1280,-30 1505,-255 1505,-455 P8.3
RS_TXD2: P7.3 U7.14 | length 1485.5
  Top Layer w8: v1(1355,480) 1358.39,483.39 U7.14
  Bottom Layer w8: P7.3 100.52,563 1212,563 1310,465 1340,465 v1(1355,480)
RS_TXD3: P8.1 U7.7 | length 892.8
  Top Layer w8: U7.7 1243.98,381.02 1295,330 1295,-20 1555,-280 P8.1
SPK+_AMP: C28.2 P4.2 P4.3 P4.4 P4.5 | length 1313.3
  Top Layer w10: C28.2 771.46,-263.54 v1(785,-250) ; P4.5@773.85,-998 773.85,-956.15 850,-880 v1(850,-515)
  Top Layer w15: P4.2@380.15,-1038 478.57,-1038 539.57,-1099 614.43,-1099 675.43,-1038 P4.5@773.85,-1038
  Bottom Layer w10: v1(785,-250) 850,-315 v1(850,-515)
T_RST: U1.56
TCK/SWCLK: P1.3 U1.49 | length 667.1
  Top Layer w8: U1.49 763.5,166.5 v1(780,150)
  Bottom Layer w8: v1(780,150) 1095,-165 1160,-165 1190,-195 P1.3@1190,-270
TDI: R2.2 U1.50 | length 99.3
  Top Layer w10: U1.50 858.58,202.05 R2.2
TDO/SWO: R4.2 U1.55 | length 98.2
  Top Layer w10: U1.55 861.06,300.47 R4.2
TIM3_CH3: R21.1 U1.26 | length 352.5
  Top Layer w10: U1.26 374.53,300.47 405,270 405,202 345,142 R21.1
TIM4_CH1: U1.58
TMS/SWDIO: P1.2 R3.2 U1.46 | length 862.7
  Top Layer w8: U1.46 653.27,46.73 675,25 R3.2 706.54,8.46 730,-15 945,-15 v1(960,0)
  Bottom Layer w8: v1(960,0) 1110,-150 1185,-150 P1.2
TTL_RXD2: U1.17 U7.12 | length 1220.2
  Top Layer w8: v1(310,520) 310,494.13 U1.17 ; v1(1325,435) 1327.8,432.2 U7.12
  Bottom Layer w8: v1(310,520) 335,545 1202.5,545 1312.5,435 v1(1325,435)
TTL_RXD3: U1.30 U7.9 | length 1519.9
  Top Layer w8: v1(265,200) 286.73,221.73 U1.30 ; v1(1355,335) 1375.43,355.43 U7.9
  Bottom Layer w8: v1(265,200) 290,225 290,398.79 376.21,485 1190,485 1340,335 v1(1355,335)
TTL_TXD2: U1.16 U7.11 | length 1181.4
  Top Layer w8: v1(350,520) 378.5,548.5 U1.16 ; v1(1355,405) 1356.61,406.61 U7.11
  Bottom Layer w8: v1(350,520) 1205,520 1320,405 v1(1355,405)
TTL_TXD3: U1.29 U7.10 | length 1487.8
  Top Layer w8: v1(263,235) 269.42,241.42 U1.29 ; v1(1355,370) 1366.02,381.02 U7.10
  Bottom Layer w8: v1(263,235) 263,393 370,500 1200,500 1330,370 v1(1355,370)
VIN: C31.1 C32.2 C35.1 C36.1 C38.2 C39.2 P9.1 P9.3 pad.1@1555,-1210 Q1.2 R25.1 R32.1 U3.5 U4.1 | length 4461.4
  Top Layer w10: R32.1 -778.46,710 -640,710 -615,685 C35.1
  Top Layer w20: U3.5 1345,-1133.54 C32.2 1360.46,-1232.07 R25.1
  Bottom Layer w40: P9.1 10,845 195,660 1305,660 1580,385 1580,270 1400,90 1400,-95 1495,-190 1495,-410 1365,-540 1365,-1020 pad.1@1555,-1210
VO_L: J1.1 P3.2 | length 89.9
  Bottom Layer w15: P3.2@-664.43,-236.45 -643.87,-257 J1.1
VO_MIC: C22.2 R15.1 | length 55
  Top Layer w10: C22.2@316.46,-642 R15.1
VO_R: C25.1 J1.2 P3.3 | length 840.8
  Top Layer w15: P3.3@-467.57,-236.45 -392.02,-312 C25.1
  Bottom Layer w15: J1.2 -488.13,-257 P3.3@-467.57,-236.45
pads on no net: P2.6 P2.7 P2.8 P3.4 P4.6 P4.7 P4.8 U1.2 U1.8 U1.9 U1.10 U1.11 U1.14 U1.15 U1.21 U1.23 U1.24 U1.25 U1.33 U1.34 U1.35 U1.36 U1.37 U1.38 U1.39 U1.44 U1.45 U1.51 U1.52 U1.53 U1.54 U1.57 U1.59 U1.61 U1.62 U2.5 U2.6 U2.7 U2.8 U2.9 U2.10 U5.1 U5.6 U5.7

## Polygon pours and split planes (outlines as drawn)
AGND on Top Layer "Top Layer-AGND" (hatched 90Degree grid 8 track 8, remove dead copper, pour order 1001): 915,-160 915,-1505 -1100,-1505 -1100,-190 -1095,-185 -1095,-165
GND on Top Layer "Top Layer-GND" (hatched 90Degree grid 8 track 8, remove dead copper, pour order 1000): -990,-140 950,-140 950,-1335 1750,-1335 1750,1045 -990,1045
AGND on Bottom Layer "Bottom Layer-AGND" (hatched 90Degree grid 8 track 8, remove dead copper, pour order 1003): 915,-160 915,-1505 -1100,-1505 -1100,-190 -1095,-185 -1095,-165
GND on Bottom Layer "Bottom Layer-GND" (hatched 90Degree grid 8 track 8, remove dead copper, pour order 1002): -990,-142 950,-142 950,-1337 1750,-1337 1750,1043 -990,1043

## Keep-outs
Keep-Out Layer:
  lines w5: -990,-1025 -842,-1025 -840,-1027 ; -990,-924.53 ccw(c-890,-924.53) -890,-1024.53 ; -989.53,965 cw(c-889.53,965) -889.53,1065 ; -840,-1234.53 ccw(c-740,-1234.53) -740,-1334.53 ; 1195,1064.53 cw(c1195,964.53) 1295,964.53 ; 1295.18,1065 1295.18,709.31 1760,709.31 ; 1659.53,-1335 ccw(c1659.53,-1235) 1759.53,-1235 ; 1660,709.53 cw(c1660,609.53) 1760,609.53
  lines w8: -990,-1025 -990,1064 1759,1064 1759,-1336 -840,-1336 -840,-1027

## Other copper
Top Layer:
  rectangle net GND: 90,-165 400,-110
  rectangle net AGND: 100,-226 360,-180
  rectangle net AGND: -620,-186 -517.37,-100
  rectangle net GND: 1010,-1260 1110,-1115
  rectangle net A3V3: 1270,-451.6 1320,-355
  rectangle net VIN: 1360.46,-1255 1590,-1160
  rectangle net D5V: 1075,-740 1155,-460
  rectangle net NetC30_2: 1010,-1000 1315,-925
  rectangle net PWR-9V: -205,124 -124,335
  rectangle net PWR-9V: -225,125 -146,181
  rectangle net PWR9V: -461,134 -368,177
  rectangle net PWR9V: -745,134 -461,257
  rectangle net PWR9V: -590,134 -450,437
  rectangle net VIN: -631,534 -454,626
  region net VIN: -451,529 -327.5,652.5 -377.22,702.22 -500.72,578.72
  rectangle net VIN: -425,640 -367,749
  region net VIN: -283,837 -321,875 -382,814 -344,776
  rectangle net VIN: -321,791 -139,875
  rectangle net VIN: -382,643 -291,814
  region net NetC30_1: 1180.46,-1020.54 1180.46,-1107.54 1224.46,-1107.54 1224.46,-1020.54
  region net NetC30_2: 1250,-960 1250,-1107.54 1315,-1107.54 1315,-960
  rectangle net OUTD: 567,-438 727,-396
  rectangle net AUDIO: 455,-332 562,-238
Bottom Layer:
  rectangle net D5V: 1120,-565 1155,-465

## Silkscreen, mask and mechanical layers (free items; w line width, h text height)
Top Overlay:
  lines w5: 990,-1310 1125,-1310 ; 453.43,995 453.43,1054 710,1054 710,995 453.43,995 ; 790,995 790,1050 864.97,1050 925,1050 925,995 790,995 ; 870,-1325 870,-1225 980,-1225 980,-1325 870,-1325 ; 1135,-1325 1264.5,-1325 1264.5,-1205 1135,-1205 1135,-1325
  lines w8: 371.45,-100.45 506.55,-100.45 506.55,-41.45 642.55,-41.45 642.55,-353.55 507.23,-353.55 507.23,-409 374,-409 374,-235 374,-103 371.45,-100.45 ; 672,-452 950,-452 950,-134 672,-134 672,-452 ; 970,330 970,775 1115,775 1115,330 970,330 ; 980,-560 980,-330 1130,-330 1130,-560 980,-560 ; 1075,-190 1075,-10 1185,-10 1185,-190 1169.97,-190 1075,-190
  text "VIN" at -325,1025 h30
  text "<" at 730,1010 h30
  text "-" at 740,1010 h30
  text "GND" at -75,930 h30
  text "VOUT" at -75,825 h30
  text "TXD2" at 94.8,550 h30
  text "RXD2" at 94.8,470 h30
  text "GND" at 105,385 h30
  text "5V" at 105,310 h30
  text "A" at 1020,-75 h60
  text "485A" at 1610,-175 h30
  text "GND" at 1015,-205 h30 r90
  text "3V3" at 1415,-205 h30 r90
  text "485B" at 1610,-215 h30
  text "1" at 1465,-285 h30
  text "SPEEX_V1" at -945,-520 h61 r270
  text "A" at 920,-535 h60
  text "TXD3" at 1495,-600 h30
  text "GND" at 1495,-645 h30
  text "RXD3" at 1495,-690 h30
  text "PCON" at 1620,-710 h30
  text ">" at 1110,-1325 h30
Mechanical 1:
  drawing of 971 lines, arcs and shapes, not listed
